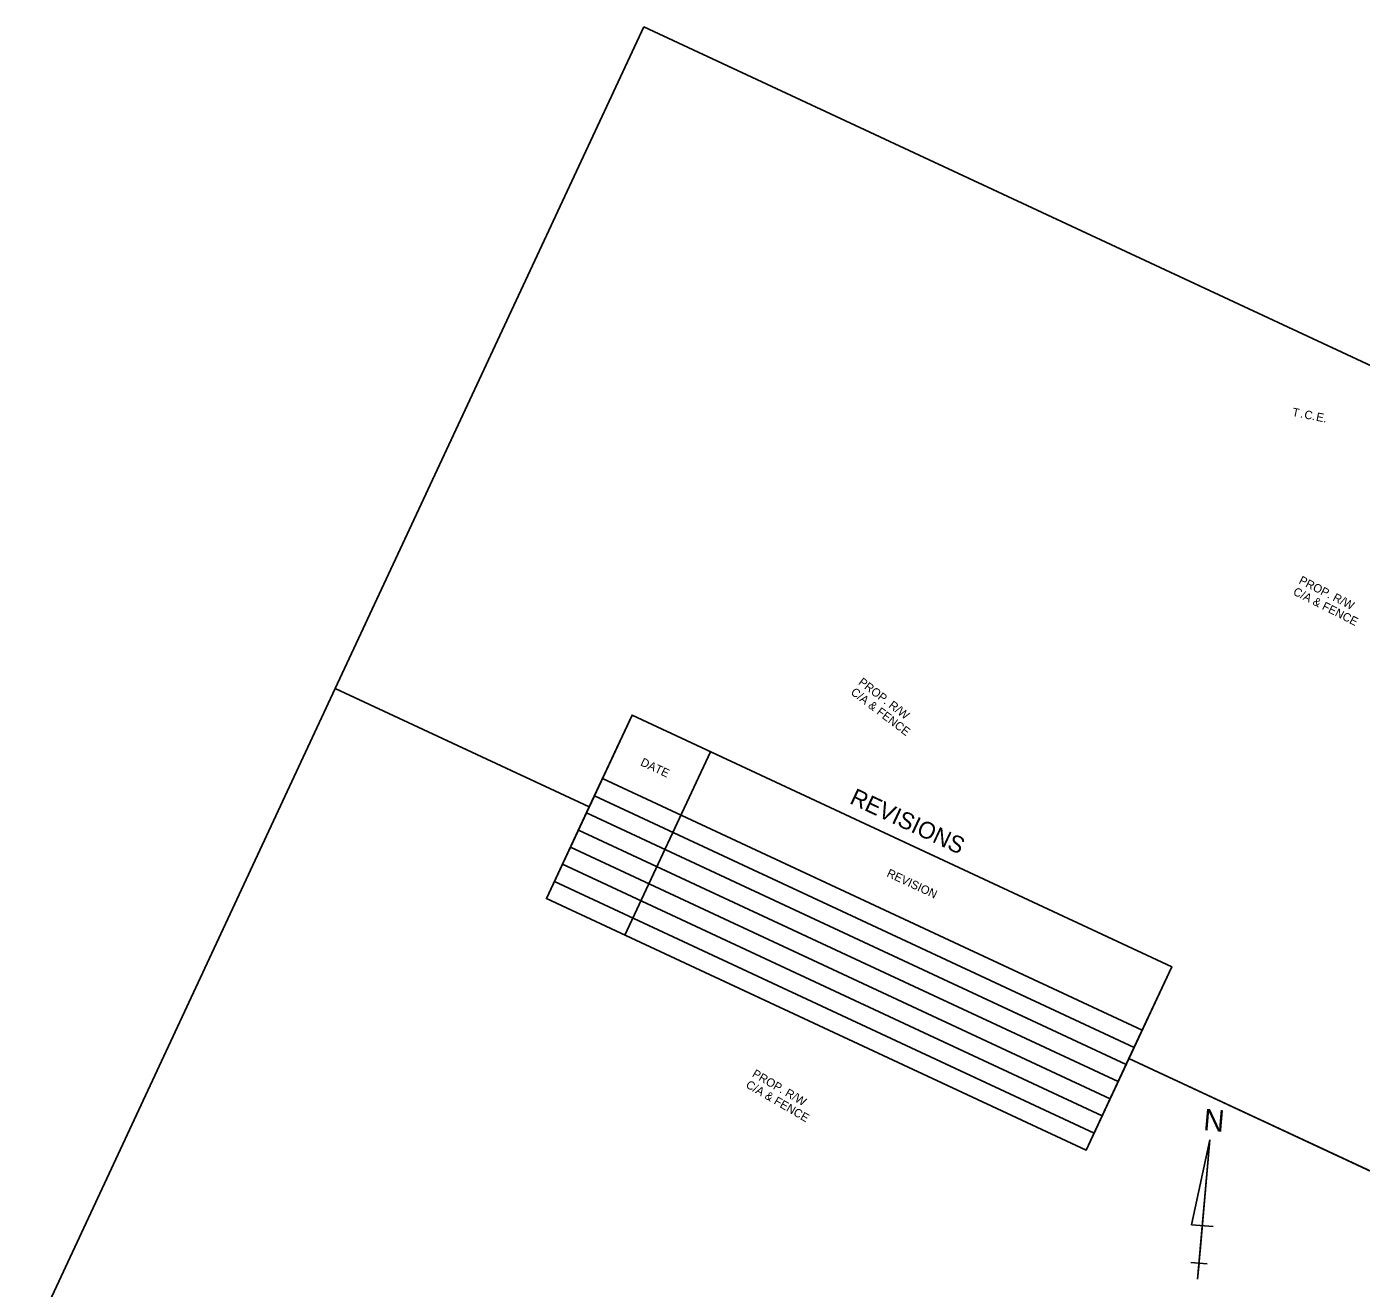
# Model space of a CAD drawing. Extents: x 980231 to 982096, y 1837566 to 1839185.
# Drawn here: x 980231 to 981183, y 1838284 to 1839185 of the extents above; entities that cross this region are included whole.
import ezdxf

# ---------------------------------------------------------------- set-up
doc = ezdxf.new("R2010")
doc.units = 0
for name, color, linetype in [('63', 7, 'Continuous'), ('G-Border-Sheet', 7, 'Continuous'), ('R_Draft', 7, 'Continuous')]:
    doc.layers.add(name, color=color, linetype=linetype)

msp = doc.modelspace()

# ---------------------------------------------------------------- linework, layer by layer
at = {"layer": '63'}
for p, q in [((981075.35, 1838390.4), (981062.32, 1838329.76)), ((981066.64, 1838290.78), (981075.35, 1838390.4)), ((981075.35, 1838390.4), (981068.65, 1838313.76)), ((981062.32, 1838329.76), (981077.65, 1838328.42)), ((981066.64, 1838290.78), (981068.65, 1838313.76)), ((981067.64, 1838302.27), (981061.89, 1838302.77)), ((981061.89, 1838302.77), (981073.39, 1838301.77)), ((981066.64, 1838290.78), (981067.64, 1838302.27))]:
    msp.add_line(p, q, dxfattribs=at)
at = {"layer": 'G-Border-Sheet'}
for p, q in [((980451.13, 1838712.53), (980632.39, 1838628)), ((980451.13, 1838712.53), (980632.39, 1838628)), ((981017.57, 1838448.39), (981261.89, 1838334.46))]:
    msp.add_line(p, q, dxfattribs=at)
for points in [[(980671.38, 1839184.86), (981846.87, 1838636.72), (981825.93, 1838591.82), (982096.33, 1838465.73), (981897.02, 1838038.3), (981572.45, 1838189.65), (981589.08, 1838225.31), (981278.52, 1838370.12), (981261.89, 1838334.46), (981017.57, 1838448.39), (981048.11, 1838513.87), (980662.93, 1838693.49), (980632.39, 1838628), (980451.13, 1838712.53)], [(980671.38, 1839184.86), (981846.87, 1838636.72), (981825.93, 1838591.82), (982096.33, 1838465.73), (981897.02, 1838038.3), (981572.45, 1838189.65), (981589.08, 1838225.31), (981278.52, 1838370.12), (981261.89, 1838334.46), (981017.57, 1838448.39), (981048.11, 1838513.87), (980662.93, 1838693.49), (980632.39, 1838628), (980451.13, 1838712.53)], [(980671.38, 1839184.86), (981846.87, 1838636.72), (981825.93, 1838591.82), (982096.33, 1838465.73), (981897.02, 1838038.3), (981572.45, 1838189.65), (981589.08, 1838225.31), (981278.52, 1838370.12), (981261.89, 1838334.46), (981017.57, 1838448.39), (981048.11, 1838513.87), (980662.93, 1838693.49), (980632.39, 1838628), (980451.13, 1838712.53)], [(981897.02, 1838038.3), (981676.77, 1837565.97), (981495.51, 1837650.49), (980230.88, 1838240.2), (980451.13, 1838712.53), (980632.39, 1838628), (980601.86, 1838562.52), (980987.04, 1838382.91), (981017.57, 1838448.39), (981261.89, 1838334.46), (981227.36, 1838260.41), (981537.92, 1838115.59), (981572.45, 1838189.65)], [(981897.02, 1838038.3), (981676.77, 1837565.97), (981495.51, 1837650.49), (980230.88, 1838240.2), (980451.13, 1838712.53), (980632.39, 1838628), (980601.86, 1838562.52), (980987.04, 1838382.91), (981017.57, 1838448.39), (981261.89, 1838334.46), (981227.36, 1838260.41), (981537.92, 1838115.59), (981572.45, 1838189.65)], [(981897.02, 1838038.3), (981676.77, 1837565.97), (981495.51, 1837650.49), (980230.88, 1838240.2), (980451.13, 1838712.53), (980632.39, 1838628), (980601.86, 1838562.52), (980987.04, 1838382.91), (981017.57, 1838448.39), (981261.89, 1838334.46), (981227.36, 1838260.41), (981537.92, 1838115.59), (981572.45, 1838189.65)], [(981897.02, 1838038.3), (981676.77, 1837565.97), (981495.51, 1837650.49), (980230.88, 1838240.2), (980451.13, 1838712.53), (980632.39, 1838628), (980601.86, 1838562.52), (980987.04, 1838382.91), (981017.57, 1838448.39), (981261.89, 1838334.46), (981227.36, 1838260.41), (981537.92, 1838115.59), (981572.45, 1838189.65)]]:
    msp.add_lwpolyline(points, close=True, dxfattribs=at)
at = {"layer": 'R_Draft'}
for p, q in [((980662.93, 1838693.49), (980601.86, 1838562.52)), ((980662.93, 1838693.49), (981048.11, 1838513.87)), ((980718.95, 1838667.36), (980657.88, 1838536.4)), ((980641.8, 1838648.17), (981026.98, 1838468.56)), ((980636.09, 1838635.93), (981021.27, 1838456.32)), ((980630.39, 1838623.7), (981015.57, 1838444.09)), ((980624.68, 1838611.46), (981009.86, 1838431.85)), ((980624.68, 1838611.46), (981009.86, 1838431.85)), ((980618.97, 1838599.23), (981004.16, 1838419.62)), ((980613.27, 1838586.99), (980998.45, 1838407.38)), ((980607.56, 1838574.76), (980992.74, 1838395.15)), ((980601.86, 1838562.52), (980987.04, 1838382.91)), ((981048.11, 1838513.87), (980987.04, 1838382.91))]:
    msp.add_line(p, q, dxfattribs=at)

# ---------------------------------------------------------------- texts
at = {"layer": '63'}
msp.add_text('N', height=15.38, rotation=355, dxfattribs=at).set_placement((981070.3, 1838397.27))
at = {"layer": 'R_Draft'}
for s, height, rotation, p in [('T', 6, 348.77013, (981133.77, 1838907.07)), ('.', 6, 348.77013, (981139.52, 1838905.93)), ('C', 6, 348.77013, (981142.39, 1838905.36)), ('.', 6, 348.77013, (981147.95, 1838904.25)), ('E', 6, 348.77013, (981150.82, 1838903.68)), ('.', 6, 348.77013, (981156.11, 1838902.63)), ('PROP. R/W', 6, 333.12632, (981138.32, 1838787.78)), ('C/A & FENCE', 6, 333.12632, (981134.25, 1838779.75)), ('C/A & FENCE', 6, 322.67844, (980818.52, 1838708.78)), ('PROP. R/W', 6, 322.67844, (980823.98, 1838715.94)), ('DATE', 6, 335, (980668.44, 1838657.82)), ('REVISIONS', 12, 335, (980817.56, 1838630.76)), ('REVISION', 6, 335, (980844.23, 1838578.6)), ('PROP. R/W', 6, 329.72279, (980748.15, 1838435.83)), ('C/A & FENCE', 6, 329.72279, (980743.62, 1838428.06))]:
    msp.add_text(s, height=height, rotation=rotation, dxfattribs=at).set_placement(p)

doc.saveas('drawing.dxf')
